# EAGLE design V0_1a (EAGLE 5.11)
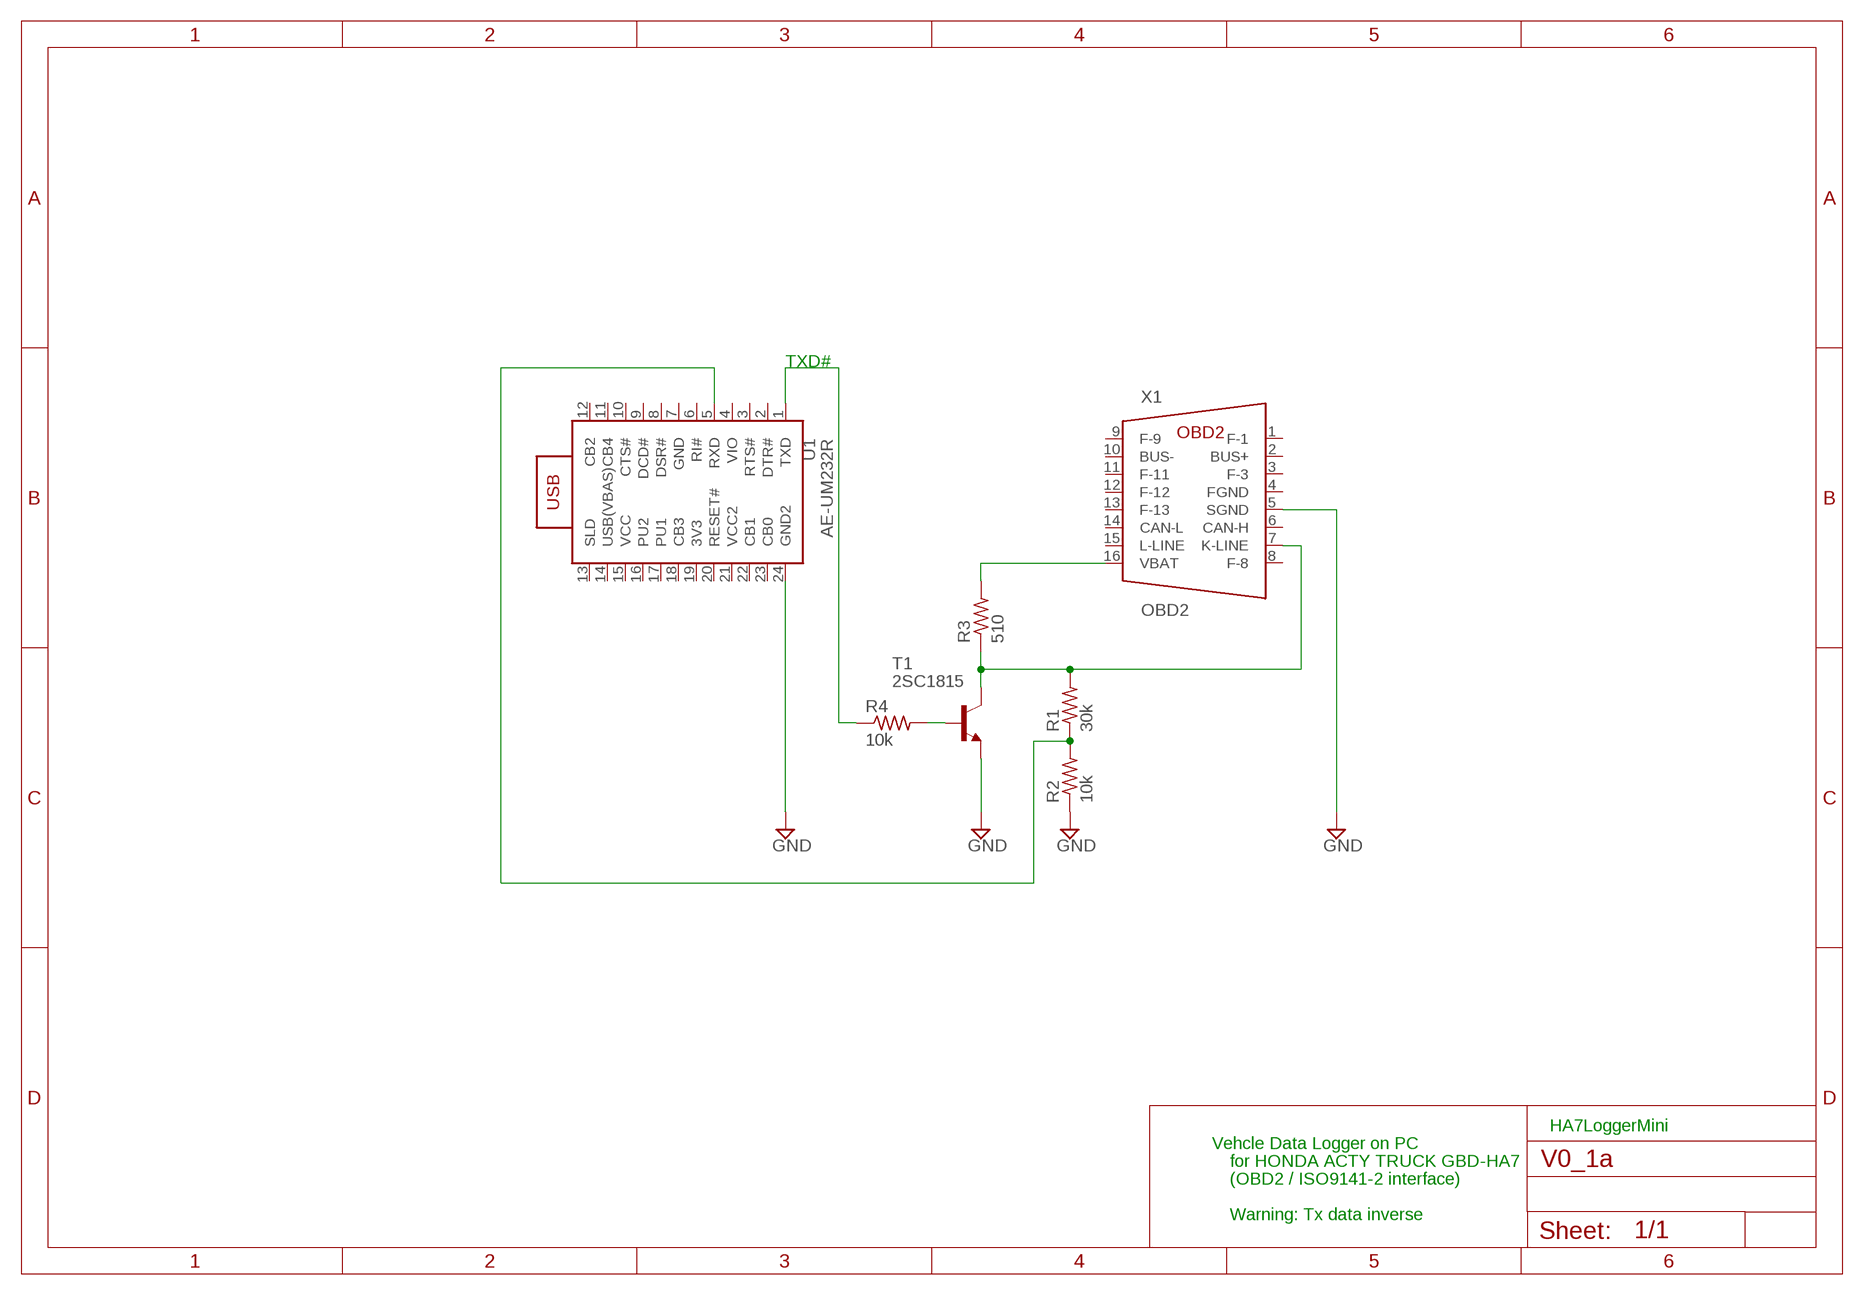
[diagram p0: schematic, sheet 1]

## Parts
R1  30k  R-US_0204/5  [0204/5]
R2  10k  R-US_0204/5  [0204/5]
R3  510  R-US_0204/5  [0204/5]
R4  10k  R-US_0204/5  [0204/5]
T1  2SC1815  BF420-NPN-TO92-BCE  [TO92-BCE]
U1  AE-UM232R  [DIL24-6]
X1  OBD2  [2X08]

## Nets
GND: R2.1 T1.E U1.24(GND2) X1.5(SGND)
N$2: R1.2 R3.1 T1.C X1.7(K-LINE)
N$4: R1.1 R2.2 U1.5(RXD)
N$6: R4.2 T1.B
N$7: R4.1 U1.1(TXD)
N$8: R3.2 X1.16(VBAT)
Unconnected: U1.2(DTR#) U1.3(RTS#) U1.4(VIO) U1.6(RI#) U1.8(DSR#) U1.9(DCD#) U1.10(CTS#) U1.11(CB4) U1.12(CB2) U1.13(SLD) U1.14(USB(VBAS)) U1.16(PU2) U1.17(PU1) U1.18(CB3) U1.20(RESET#) U1.22(CB1) U1.23(CB0) X1.1(F-1) X1.2(BUS+) X1.3(F-3) X1.6(CAN-H) X1.8(F-8) X1.9(F-9) X1.10(BUS-) X1.11(F-11) X1.12(F-12) X1.13(F-13) X1.14(CAN-L) X1.15(L-LINE)

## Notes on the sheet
- TXD#
- HA7LoggerMini
- Vehcle Data Logger on PC
- for HONDA ACTY TRUCK GBD-HA7
- (OBD2 / ISO9141-2 interface)
- Warning: Tx data inverse

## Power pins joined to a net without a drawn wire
3V3: U1.19(3V3)
FGND: X1.4(FGND)
GND: U1.7(GND)
VCC: U1.15(VCC)
VCC2: U1.21(VCC2)

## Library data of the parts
R1-R4 = rcl:R-US_: RESISTOR, American symbol
T1 = transistor:*-NPN-: NPN Transistror BF959 corrected 2008.03.06
U1 = TOG:AE-UM232R: Akizuki electric trade. USB-Serial converter module. FTDI FT232RL Chip
X1 = TOG:OBD2: OBD2 Connecter

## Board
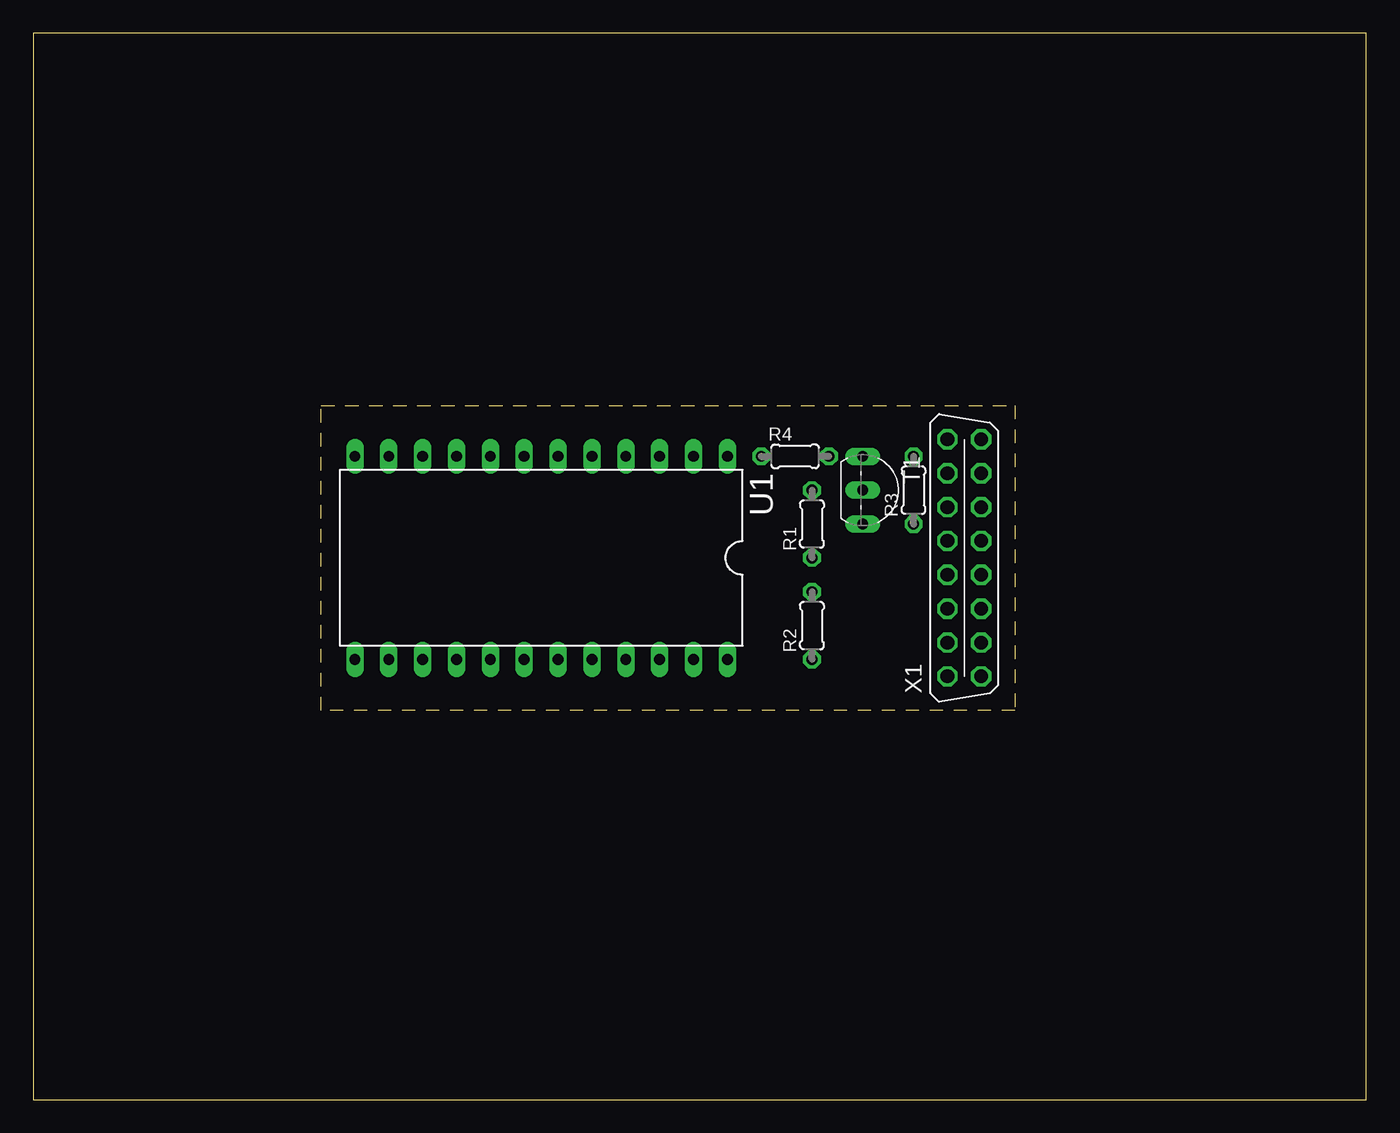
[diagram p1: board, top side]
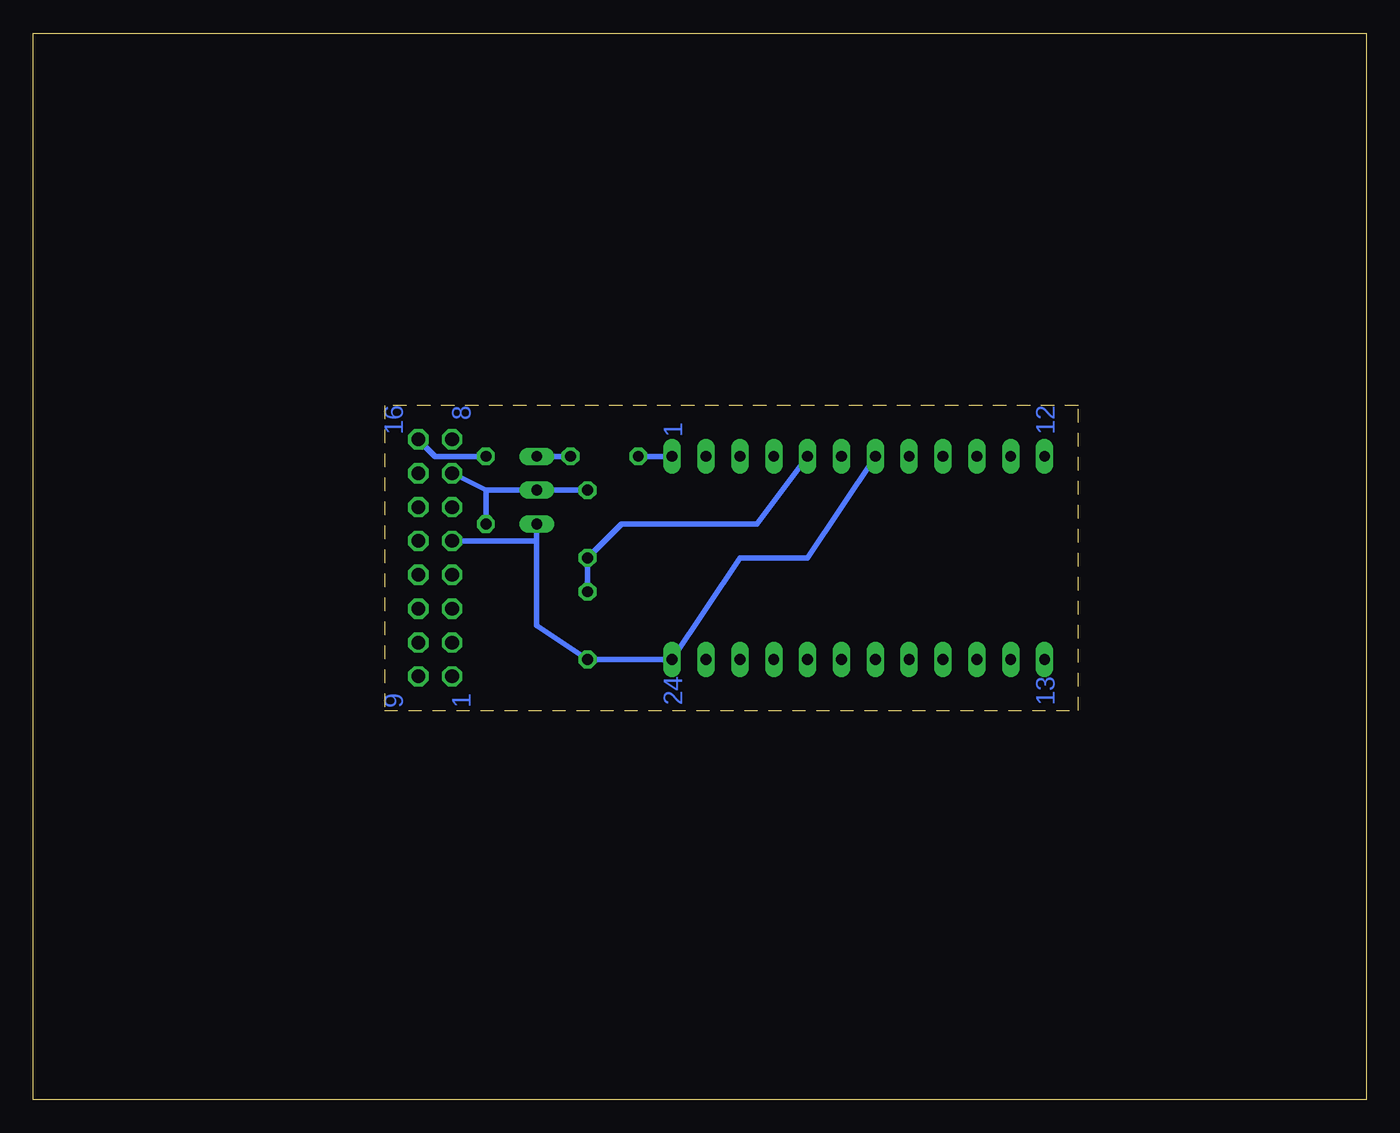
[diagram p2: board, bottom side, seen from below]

Size 100 x 80 mm. Coordinates in mm from the lower left corner, seen from the top.
Outline: 0,0 100,0 100,80 0,80 0,0
Outline: 21.59,52.07 73.66,52.07 73.66,29.21 21.59,29.21 21.59,52.07
Copper layers (1*16): Top 0.035mm / dielectric 1.5mm / Bottom 0.035mm
Design rules "default": minimum track width 10mil, minimum drill 24mil, track to track 8mil, track to pad 8mil, pad to pad 8mil, via to via 8mil, smd to smd 8mil, copper to edge 40mil, drill to drill 8mil, minimum pad ring 10mil, minimum via ring 8mil, stop-mask expansion 4mil, vias tented up to drill 0mil, thermal gap 10mil

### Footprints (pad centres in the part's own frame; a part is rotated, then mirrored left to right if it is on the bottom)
0204/5 = drill 0.813 octagon: 1 -2.54,0; 2 2.54,0
TO92-BCE = drill 0.813 long: B -2.54,0; C 0,0; E 2.54,0
DIL24-6 = drill 0.813 long: 1 -13.97,-7.62; 2 -11.43,-7.62; 3 -8.89,-7.62; 4 -6.35,-7.62; 5 -3.81,-7.62; 6 -1.27,-7.62; 7 1.27,-7.62; 8 3.81,-7.62; 9 6.35,-7.62; 10 8.89,-7.62; 11 11.43,-7.62; 12 13.97,-7.62; 13 13.97,7.62; 14 11.43,7.62; 15 8.89,7.62; 16 6.35,7.62; 17 3.81,7.62; 18 1.27,7.62; 19 -1.27,7.62; 20 -3.81,7.62; 21 -6.35,7.62; 22 -8.89,7.62; 23 -11.43,7.62; 24 -13.97,7.62
2X08 = drill 1.016 octagon: 1 -8.89,1.27; 2 -6.35,1.27; 3 -1.27,1.27; 4 -3.81,1.27; 5 1.27,1.27; 6 3.81,1.27; 7 6.35,1.27; 8 8.89,1.27; 9 -8.89,-1.27; 10 -6.35,-1.27; 11 -3.81,-1.27; 12 -1.27,-1.27; 13 1.27,-1.27; 14 3.81,-1.27; 15 6.35,-1.27; 16 8.89,-1.27

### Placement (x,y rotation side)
R1  58.42,43.18 90 top
R2  58.42,35.56 90 top
R3  66.04,45.72 90 top
R4  57.15,48.26 0 top
T1  62.23,45.72 270 top
U1  38.1,40.64 180 top
X1  69.85,40.64 90 top

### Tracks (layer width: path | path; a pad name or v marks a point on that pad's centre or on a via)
GND
  Bottom 0.406: U1.7 41.91,40.64 46.99,40.64 U1.24 R2.1 62.23,35.56 62.23,41.91 | 62.23,41.91 T1.E | 62.23,41.91 X1.5
N$2
  Bottom 0.406: 66.04,45.72 T1.C R1.2 | 66.04,45.72 R3.1 | 66.04,45.72 X1.7
N$4
  Bottom 0.406: U1.5 45.72,43.18 55.88,43.18 R1.1 R2.2
N$6
  Bottom 0.406: T1.B R4.2
N$7
  Bottom 0.406: R4.1 U1.1
N$8
  Bottom 0.406: R3.2 69.85,48.26 X1.16

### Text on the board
Bottom: 12 | 8 | 16 | 1 | 13 | 24 | 1 | 9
